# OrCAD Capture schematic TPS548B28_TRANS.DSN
size E; title: TPS548B28 2.7-V to 16-V Input, 20-A Synchronous Step-down; rev: 1.0; note: Datasheet:SNVSBC5                                  EVM:SNVU662; note: Synchronous Step Down Converter
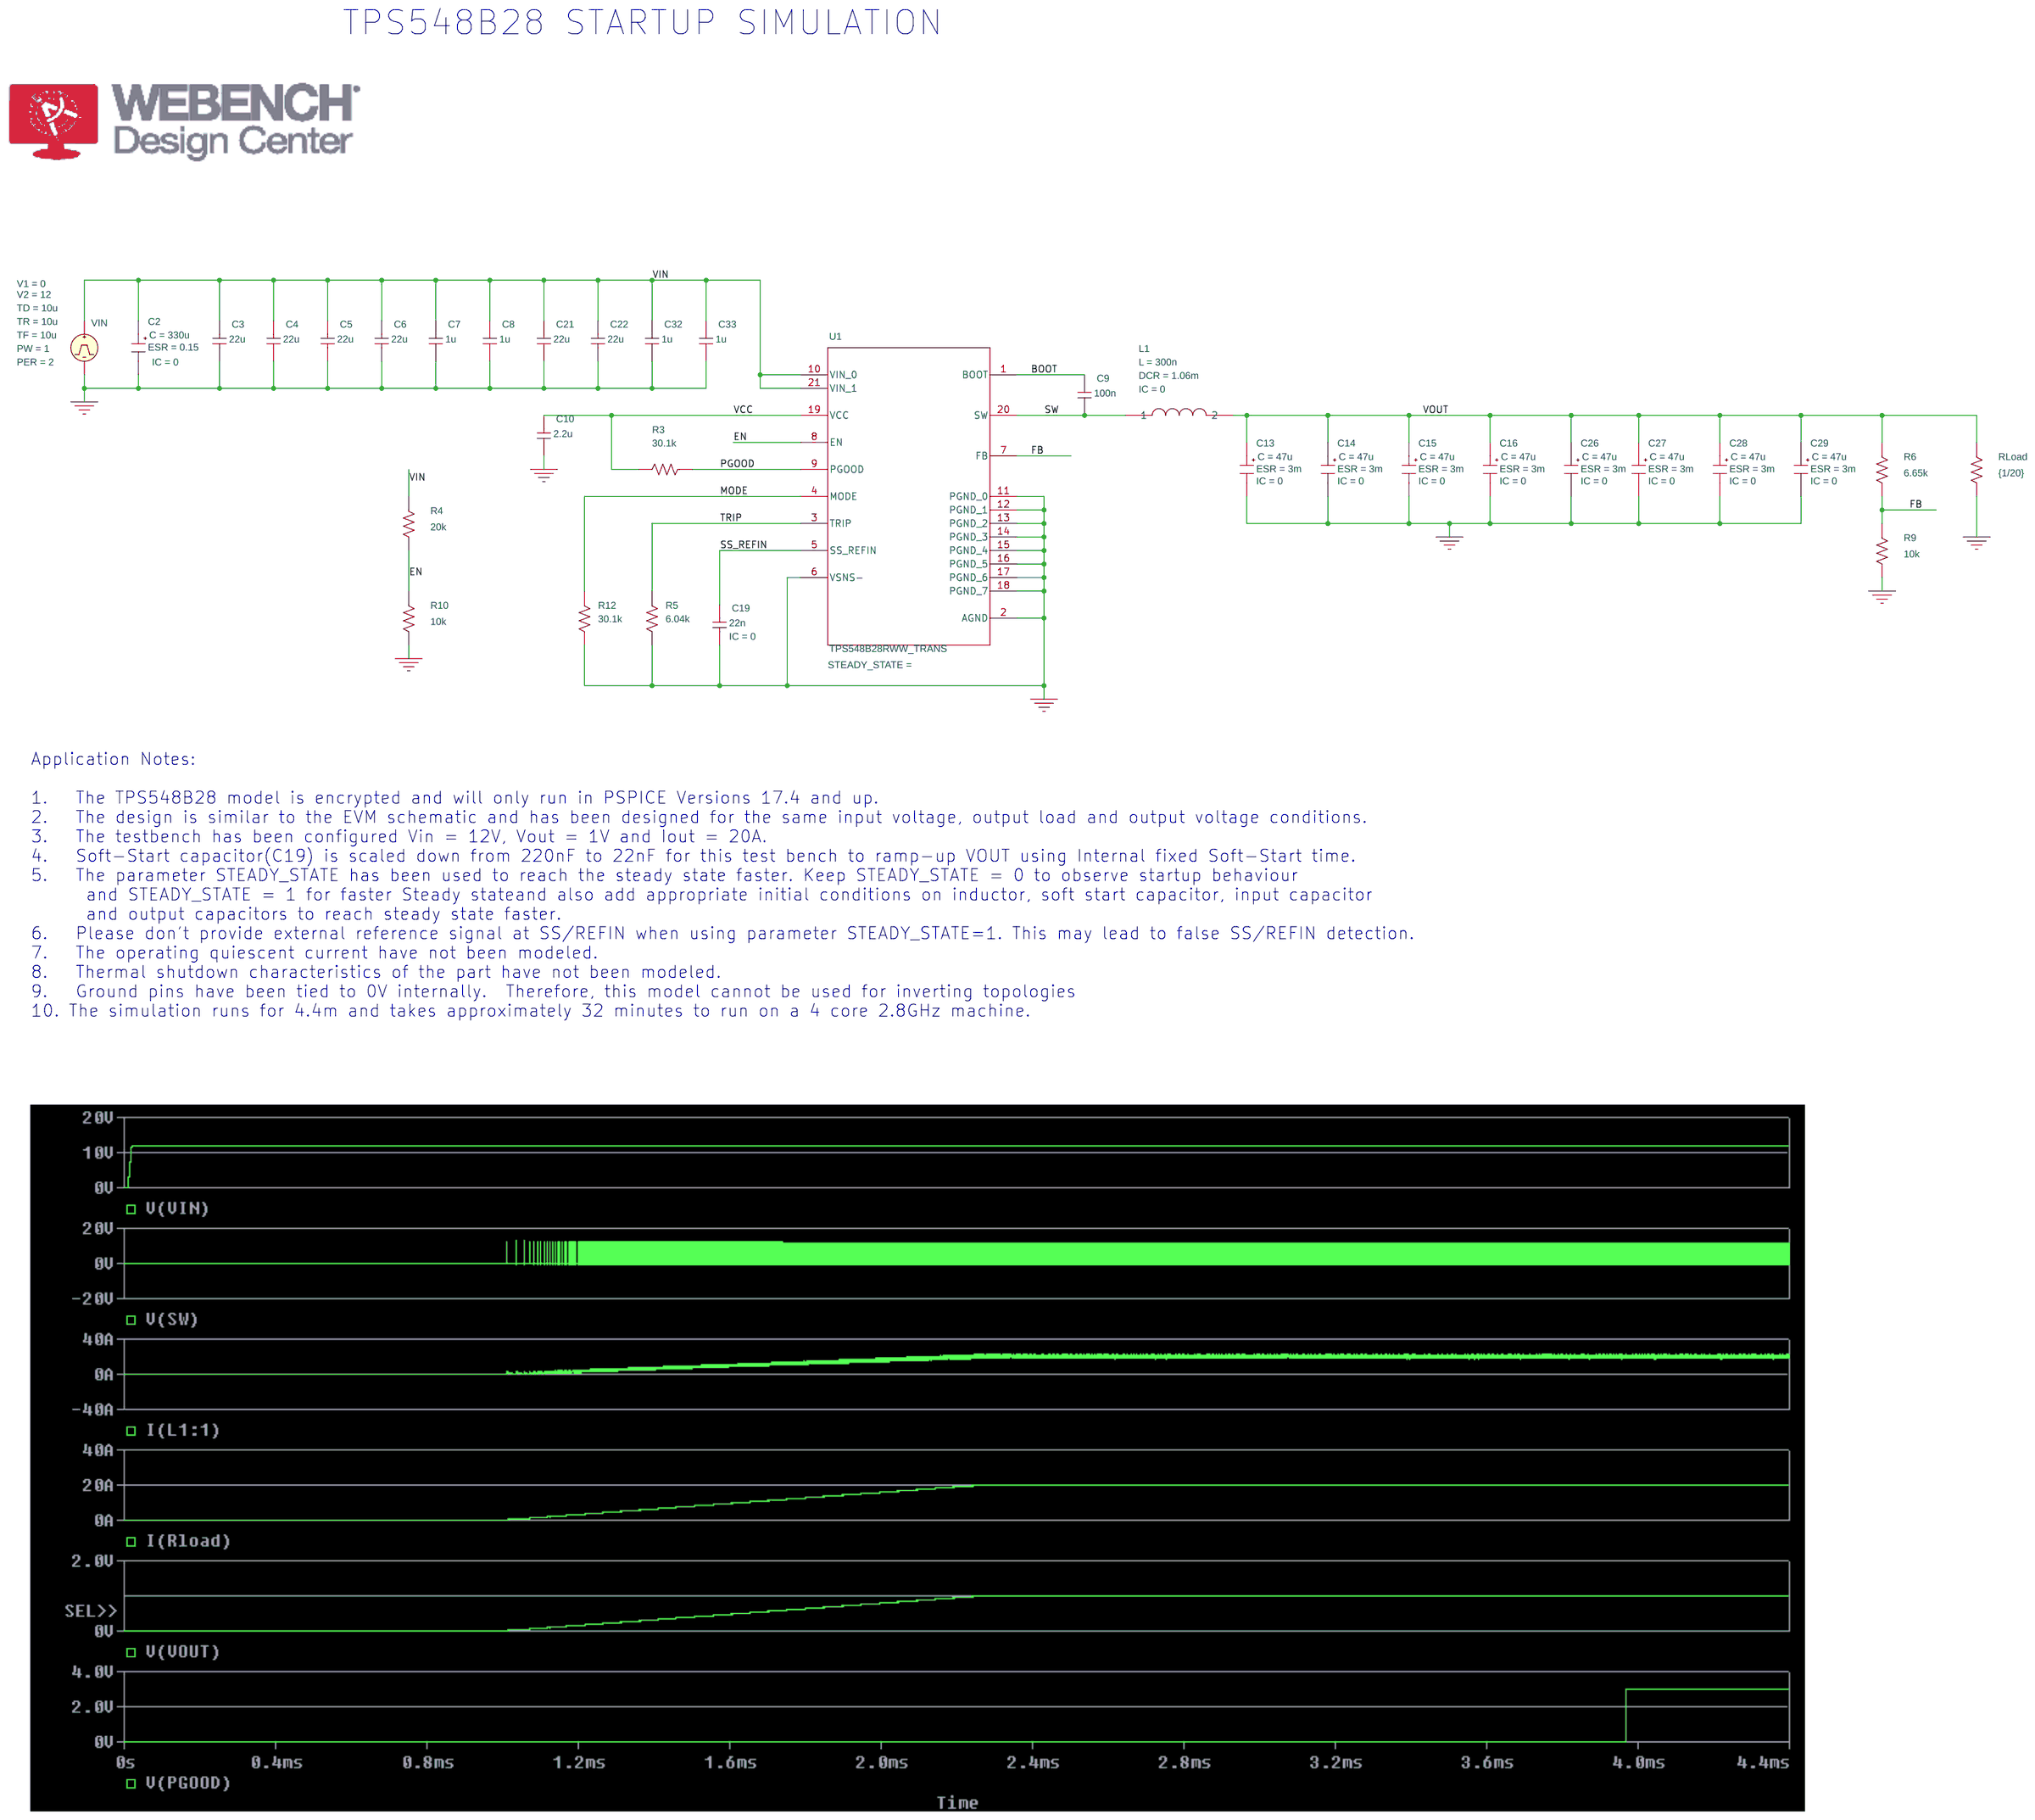
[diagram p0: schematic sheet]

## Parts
C2  CESR
C3  22u  [RAD/CK05]
C4  22u  [RAD/CK05]
C5  22u  [RAD/CK05]
C6  22u  [RAD/CK05]
C7  1u  [RAD/CK05]
C8  1u  [RAD/CK05]
C9  100n  [RAD/CK05]
C10  2.2u  [RAD/CK05]
C13  CESR
C14  CESR
C15  CESR
C16  CESR
C19  22n  [RAD/CK05]
C21  22u  [RAD/CK05]
C22  22u  [RAD/CK05]
C26  CESR
C27  CESR
C28  CESR
C29  CESR
C32  1u  [RAD/CK05]
C33  1u  [RAD/CK05]
L1  LDCR
R3  30.1k  [AX/RC05]
R4  20k  [AX/RC05]
R5  6.04k  [AX/RC05]
R6  6.65k  [AX/RC05]
R9  10k  [AX/RC05]
R10  10k  [AX/RC05]
R12  30.1k  [AX/RC05]
RLoad  {1/20}  [AX/RC05]
U1  TPS548B28RWW_TRANS  [RWW0021A-MFG]
VIN  VPULSE

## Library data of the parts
C2 = CESR_0: C: 330u; ESR: 0.15; IC: 0; PSpiceTemplate: X^@REFDES %IN %OUT @MODEL PARAMS:  ?C|C=@C||C=100u|  ?ESR|ESR=@ESR||ESR=0.01| ?X|X=@X||X=2|  ?IC|IC=@IC||IC=2|; X: 1
C3-C10 C21 C22 C32 C33 = c_0
C13-C16 C26-C29 = CESR_0: C: 47u; ESR: 3m; IC: 0; PSpiceTemplate: X^@REFDES %IN %OUT @MODEL PARAMS:  ?C|C=@C||C=100u|  ?ESR|ESR=@ESR||ESR=0.01| ?X|X=@X||X=2|  ?IC|IC=@IC||IC=2|; X: 1
C19 = c_0: IC: 0
L1 = LDCR: DCR: 1.06m; IC: 0; L: 300n
R3-R6 R9 R10 R12 RLoad = R
U1 = TPS548B28RWW_TRANS
VIN = VPULSE: PER: 2; PW: 1; TD: 10u; TF: 10u; TR: 10u; V1: 0; V2: 12

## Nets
VCC: C10.1 R3.2 U1.19(VCC)
VIN: C2.1(IN) C3.1 C4.1 C5.1 C6.1 C7.1 C8.1 C21.1 C22.1 C32.1 C33.1 R4.1 U1.10(VIN_0) U1.21(VIN_1) VIN.1(+)
0: C2.2(OUT) C3.2 C4.2 C5.2 C6.2 C7.2 C8.2 C10.2 C13.2(OUT) C14.2(OUT) C15.2(OUT) C16.2(OUT) C19.2 C21.2 C22.2 C26.2(OUT) C27.2(OUT) C28.2(OUT) C29.2(OUT) C32.2 C33.2 R5.2 R9.2 R10.2 R12.2 RLoad.2 U1.2(AGND) U1.6(VSNS-) U1.11(PGND_0) U1.12(PGND_1) U1.13(PGND_2) U1.14(PGND_3) U1.15(PGND_4) U1.16(PGND_5) U1.17(PGND_6) U1.18(PGND_7) VIN.2(-)
BOOT: C9.1 U1.1(BOOT)
EN: R4.2 R10.1 U1.8(EN)
FB: R6.2 R9.1 U1.7(FB)
MODE: R12.1 U1.4(MODE)
PGOOD: R3.1 U1.9(PGOOD)
SS_REFIN: C19.1 U1.5(SS_REFIN)
SW: C9.2 L1.1 U1.20(SW)
TRIP: R5.1 U1.3(TRIP)
VOUT: C13.1(IN) C14.1(IN) C15.1(IN) C16.1(IN) C26.1(IN) C27.1(IN) C28.1(IN) C29.1(IN) L1.2 R6.1 RLoad.1

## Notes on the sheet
- TPS548B28 STARTUP SIMULATION
- Application Notes:
  1.   The TPS548B28 model is encrypted and will only run in PSPICE Versions 17.4 and up.
  2.   The design is similar to the EVM schematic and has been designed for the same input voltage, output load and output voltage conditions.
  3.   The testbench has been configured Vin = 12V, Vout = 1V and Iout = 20A.
  4.   Soft-Start capacitor(C19) is scaled down from 220nF to 22nF for this test bench to ramp-up VOUT using Internal fixed Soft-Start time.
  5.   The parameter STEADY_STATE has been used to reach the steady state faster. Keep STEADY_STATE = 0 to observe startup behaviour
        and STEADY_STATE = 1 for faster Steady stateand also add appropriate initial conditions on inductor, soft start capacitor, input capacitor
        and output capacitors to reach steady state faster.
  6.   Please don't provide external reference signal at SS/REFIN when using parameter STEADY_STATE=1. This may lead to false SS/REFIN detection.
  7.   The operating quiescent current have not been modeled.
  8.   Thermal shutdown characteristics of the part have not been modeled.
  9.   Ground pins have been tied to 0V internally.  Therefore, this model cannot be used for inverting topologies
  10. The simulation runs for 4.4m and takes approximately 32 minutes to run on a 4 core 2.8GHz machine.
